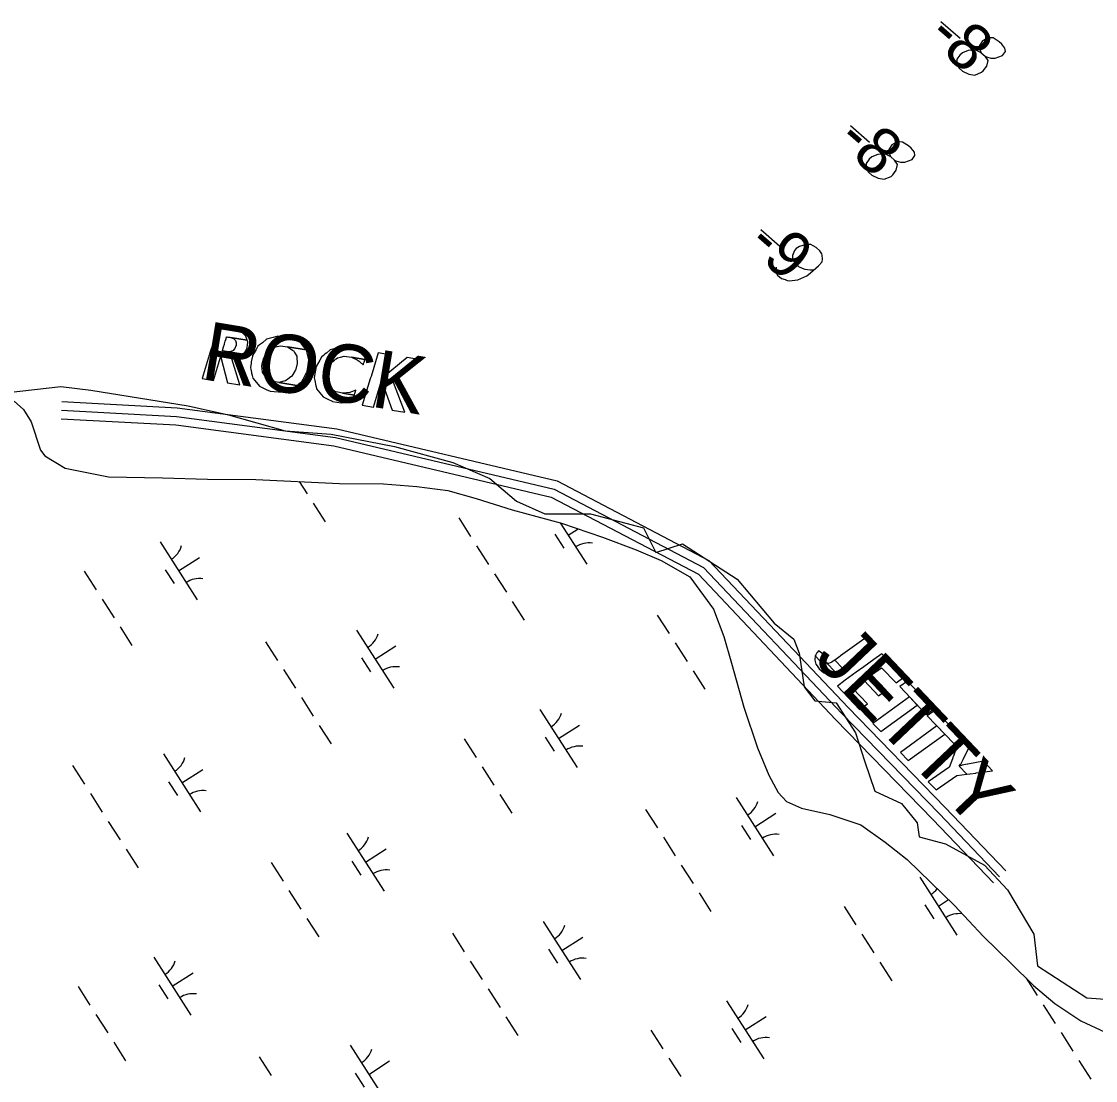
# Model space of a CAD drawing. Extents: x 3962991 to 3983549, y 181631 to 204078.
# Drawn here: x 3969320 to 3970099, y 196180 to 196948 of the extents above; entities that cross this region are included whole.
import ezdxf

# ---------------------------------------------------------------- set-up
doc = ezdxf.new("R2010")
doc.units = 0
for name, color, linetype in [('V-ANNO-MASK', 7, 'Continuous'), ('V-ANNO-MASK2', 7, 'Continuous'), ('V-RIVR-EDGE', 7, 'Continuous'), ('V-RIVR-IDEN', 7, 'Continuous'), ('V-RIVR-RANG', 7, 'Continuous'), ('V-WETL-SWMP', 7, 'Continuous')]:
    doc.layers.add(name, color=color, linetype=linetype)

msp = doc.modelspace()

# ---------------------------------------------------------------- linework, layer by layer
at = {"layer": 'V-ANNO-MASK2'}
for p, q in [((3969986.67, 196948.08), (3970000.6, 196935.96)), ((3969921.03, 196872.65), (3969934.96, 196860.53)), ((3969855.94, 196797.25), (3969869.87, 196785.13))]:
    msp.add_line(p, q, dxfattribs=at)
for points in [[(3970015.92, 196925.43), (3970018.7, 196923.01), (3970019.67, 196922.52), (3970022.93, 196921.43), (3970026.1, 196921.47), (3970031.38, 196923.51), (3970033.43, 196926.27), (3970033.08, 196928.68), (3970030.81, 196931.7), (3970028.82, 196933.43), (3970024.52, 196936.13), (3970021.89, 196936.32), (3970018.97, 196935.37), (3970016.81, 196934.1), (3970014.61, 196930.76), (3970014.37, 196928.88), (3970015.92, 196925.43), (3970012.04, 196927.41), (3970006.46, 196927.02), (3970002.27, 196925.42), (3970000.34, 196923.6), (3969998.11, 196920.65), (3969998.17, 196917.1), (3969999.87, 196914.22), (3970002.26, 196912.15), (3970006.9, 196909.85), (3970011.25, 196909.22), (3970016.15, 196911.24), (3970017.39, 196912.26), (3970019.96, 196915.62), (3970020.8, 196919.79), (3970018.7, 196923.01)], [(3969950.27, 196850), (3969953.06, 196847.57), (3969954.03, 196847.08), (3969957.28, 196846), (3969960.46, 196846.03), (3969965.74, 196848.08), (3969967.79, 196850.84), (3969967.43, 196853.24), (3969965.17, 196856.27), (3969963.18, 196858), (3969958.88, 196860.69), (3969956.25, 196860.88), (3969953.32, 196859.93), (3969951.17, 196858.66), (3969948.97, 196855.33), (3969948.72, 196853.44), (3969950.27, 196850), (3969946.39, 196851.97), (3969940.81, 196851.58), (3969936.62, 196849.98), (3969934.69, 196848.17), (3969932.47, 196845.21), (3969932.53, 196841.66), (3969934.22, 196838.79), (3969936.61, 196836.71), (3969941.26, 196834.41), (3969945.6, 196833.78), (3969950.51, 196835.8), (3969951.75, 196836.82), (3969954.32, 196840.18), (3969955.15, 196844.35), (3969953.06, 196847.57)], [(3969867.18, 196769.99), (3969866.87, 196766.41), (3969868.14, 196764.26), (3969870.93, 196761.83), (3969873.61, 196760.9), (3969875.15, 196760.26), (3969876.66, 196759.99), (3969882.96, 196760.8), (3969889.31, 196763.67), (3969892.16, 196765.74), (3969897.98, 196770.82), (3969900.57, 196773.8), (3969900.82, 196775.69), (3969900.61, 196778.66), (3969900.36, 196779.58), (3969898.89, 196781.91), (3969896.3, 196784.16), (3969893.97, 196785.5), (3969892.23, 196786.31), (3969888.85, 196786.45), (3969884.09, 196785), (3969881.76, 196783.53), (3969880.38, 196781.94), (3969879.12, 196778.48), (3969879.05, 196776.79), (3969879.75, 196774.79), (3969881.62, 196772.11), (3969883.41, 196770.55), (3969886.12, 196769.25), (3969888.03, 196768.63), (3969891.8, 196768.14), (3969893.86, 196768.1), (3969894.98, 196768.18)]]:
    msp.add_lwpolyline(points, dxfattribs=at)
for points in [[(3969456.06, 196706.12), (3969450.9, 196689.14), (3969459.02, 196687.8), (3969464.17, 196704.77), (3969464.3, 196705.19), (3969473.83, 196703.61), (3969474.95, 196703.75), (3969478.33, 196704.92), (3969480.62, 196706.82), (3969465.55, 196709.32), (3969465.55, 196709.33), (3969465.62, 196709.56), (3969465.8, 196710.15), (3969465.93, 196710.57), (3969466.46, 196712.31), (3969467.05, 196714.24), (3969467.08, 196714.36), (3969467.7, 196716.39), (3969468.2, 196718.04), (3969468.3, 196718.37), (3969468.53, 196719.12), (3969468.62, 196719.41), (3969468.63, 196719.42), (3969483.63, 196716.94), (3969482.65, 196719.87), (3969479.54, 196723.02), (3969475.08, 196724.9), (3969469.9, 196725.86), (3969462.43, 196727.09), (3969462.39, 196727), (3969462.07, 196725.92), (3969461.31, 196723.41), (3969460.5, 196720.77), (3969460.5, 196720.76), (3969460.41, 196720.46), (3969460.19, 196719.71), (3969460.08, 196719.38), (3969459.58, 196717.74), (3969458.97, 196715.71), (3969458.93, 196715.59), (3969458.34, 196713.66), (3969457.82, 196711.91), (3969457.69, 196711.5), (3969457.51, 196710.91), (3969457.44, 196710.67), (3969457.44, 196710.66), (3969456.77, 196708.49), (3969456.27, 196706.84), (3969456.18, 196706.53)], [(3969471.05, 196708.66), (3969468.6, 196708.82), (3969480.64, 196706.83), (3969480.88, 196707.03), (3969481.51, 196707.55), (3969481.71, 196707.95), (3969482.58, 196709.64), (3969483.53, 196711.51), (3969483.55, 196711.64), (3969483.54, 196711.64), (3969483.78, 196713.73), (3969483.97, 196715.42), (3969484.02, 196715.76), (3969483.74, 196716.6), (3969483.63, 196716.93), (3969471.51, 196718.93), (3969473.57, 196718.28), (3969474.59, 196717.33), (3969475.05, 196716.9), (3969475.65, 196715.07), (3969475.49, 196712.97), (3969475.44, 196712.85), (3969474.71, 196710.95), (3969473.18, 196709.37), (3969472.29, 196709.08)], [(3969469.53, 196719.27), (3969471.51, 196718.93), (3969483.63, 196716.93), (3969483.63, 196716.94)], [(3969497.33, 196681.33), (3969500.13, 196680.03), (3969509.07, 196679.39), (3969512.02, 196680.35), (3969516.99, 196681.95), (3969519.64, 196684.15), (3969506.4, 196686.35), (3969501.35, 196687.23), (3969497.27, 196689.79), (3969497.21, 196689.89), (3969496.11, 196691.66), (3969496.1, 196691.66), (3969494.7, 196693.91), (3969494.67, 196694.29), (3969494.54, 196695.88), (3969494.3, 196698.93), (3969494.37, 196699.21), (3969494.36, 196699.22), (3969494.54, 196699.91), (3969495.64, 196704.16), (3969495.63, 196704.17), (3969495.65, 196704.24), (3969495.81, 196704.48), (3969497.89, 196707.7), (3969498.6, 196708.8), (3969498.63, 196708.82), (3969501.44, 196710.91), (3969502.74, 196711.86), (3969502.79, 196711.91), (3969507.72, 196713), (3969507.75, 196713.01), (3969512.8, 196712.2), (3969526.57, 196709.92), (3969523.69, 196713.39), (3969521.62, 196715.88), (3969516.51, 196718.25), (3969514.23, 196719.31), (3969514.22, 196719.32), (3969505.69, 196720.04), (3969502.36, 196719.07), (3969497.65, 196717.7), (3969494.6, 196715.21), (3969494.57, 196715.19), (3969494.56, 196715.18), (3969492.61, 196713.59), (3969492.55, 196713.55), (3969491.36, 196712.58), (3969490.01, 196710.24), (3969490, 196710.22), (3969489.36, 196709.11), (3969487.49, 196705.86), (3969487.34, 196705.62), (3969487.3, 196705.54), (3969486.55, 196701.23), (3969486.42, 196700.53), (3969486.38, 196700.24), (3969485.87, 196697.32), (3969486.24, 196695.68), (3969486.33, 196695.3), (3969486.81, 196693.2), (3969487.19, 196691.55), (3969487.21, 196691.46), (3969487.67, 196689.5), (3969487.71, 196689.44), (3969490.21, 196686.38), (3969492.52, 196683.58)], [(3969468.59, 196708.82), (3969466.74, 196709.12), (3969480.62, 196706.82), (3969480.64, 196706.83)], [(3969506.53, 196686.38), (3969506.4, 196686.35), (3969519.64, 196684.15), (3969519.7, 196684.2), (3969519.69, 196684.2), (3969521.58, 196685.77), (3969521.68, 196685.84), (3969521.67, 196685.84), (3969523.27, 196687.16), (3969524.26, 196689.01), (3969524.44, 196689.36), (3969524.44, 196689.36), (3969525.21, 196690.8), (3969526.68, 196693.57), (3969526.83, 196693.84), (3969527.18, 196694.5), (3969527.82, 196698.83), (3969527.84, 196698.91), (3969527.87, 196699.17), (3969528.39, 196702.65), (3969528.08, 196703.91), (3969528.07, 196703.94), (3969527.41, 196706.6), (3969527.11, 196707.83), (3969527.1, 196707.88), (3969526.61, 196709.87), (3969526.59, 196709.89), (3969526.57, 196709.92), (3969512.8, 196712.2), (3969512.85, 196712.16), (3969512.88, 196712.14), (3969516.99, 196709.56), (3969517.1, 196709.49), (3969517.85, 196708.19), (3969519.47, 196705.36), (3969519.48, 196705.34), (3969519.58, 196704.11), (3969519.91, 196700.49), (3969519.84, 196700.23), (3969519.82, 196700.16), (3969518.73, 196695.9), (3969518.55, 196695.21), (3969518.38, 196694.94), (3969516.64, 196692.22), (3969515.73, 196690.8), (3969515.33, 196690.49), (3969513.16, 196688.84), (3969511.45, 196687.54), (3969511.22, 196687.48)], [(3969545.26, 196672.69), (3969545.34, 196672.65), (3969551.77, 196671.61), (3969556.92, 196671.83), (3969559.67, 196672.47), (3969559.96, 196672.53), (3969561.28, 196677.27), (3969552.74, 196678.68), (3969549.31, 196679.3), (3969547.6, 196679.61), (3969544.89, 196681.31), (3969543.52, 196682.17), (3969540.96, 196686.29), (3969540.79, 196688.24), (3969540.55, 196691.31), (3969541.88, 196696.52), (3969541.91, 196696.62), (3969544.85, 196701.16), (3969546.8, 196702.62), (3969547.67, 196703.26), (3969547.99, 196703.5), (3969549.05, 196704.28), (3969551.24, 196704.77), (3969554, 196705.39), (3969559.11, 196704.71), (3969568.97, 196703.07), (3969569.84, 196705.76), (3969570.1, 196706.56), (3969566.79, 196709.06), (3969563.21, 196710.53), (3969560.43, 196711.67), (3969560.43, 196711.67), (3969551.9, 196712.4), (3969549.98, 196711.84), (3969545.72, 196710.6), (3969543.86, 196710.06), (3969540.98, 196707.71), (3969540.8, 196707.57), (3969539.71, 196706.68), (3969538.84, 196705.97), (3969537.87, 196705.18), (3969537.57, 196704.93), (3969537.15, 196704.22), (3969536.21, 196702.59), (3969533.57, 196698), (3969533.51, 196697.9), (3969532.59, 196692.63), (3969532.07, 196689.68), (3969532.53, 196687.68), (3969533.42, 196683.85), (3969533.57, 196683.19), (3969533.87, 196681.89), (3969533.88, 196681.86), (3969533.92, 196681.8), (3969538.61, 196676.07), (3969538.72, 196675.94), (3969542.03, 196674.29)], [(3969464.41, 196704.73), (3969469.32, 196686.09), (3969478.21, 196684.62), (3969472.31, 196703.42), (3969473.83, 196703.61), (3969464.3, 196705.19)], [(3969566.68, 196700.11), (3969567.7, 196699.16), (3969567.94, 196699.9), (3969568.03, 196700.18), (3969568.33, 196701.09), (3969568.59, 196701.9), (3969568.92, 196702.92), (3969568.97, 196703.07), (3969559.11, 196704.71), (3969559.68, 196704.45), (3969563.3, 196702.78), (3969564.71, 196701.69), (3969566.29, 196700.47)], [(3969572.85, 196689.05), (3969567.04, 196669.9), (3969575.15, 196668.56), (3969580.96, 196687.71), (3969589.73, 196686.26), (3969589.48, 196686.94), (3969590.66, 196687.9), (3969581.48, 196689.42), (3969586.68, 196706.51), (3969578.57, 196707.86), (3969573.37, 196690.76), (3969573.04, 196689.67)], [(3969599.5, 196704.39), (3969581.48, 196689.42), (3969590.66, 196687.9), (3969609.11, 196702.8)], [(3969580.96, 196687.71), (3969588.66, 196666.32), (3969597.79, 196664.81), (3969589.73, 196686.26)], [(3969552.94, 196678.7), (3969552.74, 196678.68), (3969561.28, 196677.27), (3969561.29, 196677.32), (3969561.3, 196677.34), (3969561.64, 196678.54), (3969561.8, 196679.14), (3969562.25, 196680.75), (3969559.18, 196679.58), (3969558.03, 196679.14), (3969553.05, 196678.71)], [(3969913.28, 196487.7), (3969909.67, 196485.07), (3969915.31, 196479.13), (3969918.94, 196481.74), (3969919.6, 196482.23), (3969938, 196495.59), (3969932.33, 196501.57), (3969913.94, 196488.18)], [(3969895.96, 196488.81), (3969895.56, 196488.06), (3969907.88, 196475.09), (3969908.86, 196475.22), (3969910.31, 196476.02), (3969910.35, 196476.03), (3969903.34, 196483.41), (3969903.01, 196484.44), (3969902.88, 196484.88), (3969903.37, 196486.07), (3969903.4, 196486.16), (3969903.96, 196486.83), (3969904.1, 196486.98), (3969904.29, 196487.2), (3969903.01, 196488.12), (3969902.13, 196488.75), (3969898.37, 196491.45), (3969897.99, 196491.73), (3969897.22, 196490.84), (3969897.09, 196490.69), (3969896.78, 196490.32), (3969896.75, 196490.3)], [(3969896.87, 196480.82), (3969898.33, 196478.74), (3969901.39, 196476.06), (3969901.85, 196475.89), (3969905.01, 196474.69), (3969905.13, 196474.71), (3969907.88, 196475.09), (3969895.56, 196488.06), (3969895.2, 196485.17), (3969895.25, 196484.97), (3969896.01, 196482.04)], [(3969904.81, 196482.55), (3969903.34, 196483.41), (3969910.35, 196476.03), (3969910.78, 196476.26), (3969910.96, 196476.37), (3969912.03, 196476.94), (3969912.11, 196476.99), (3969912.9, 196477.42), (3969913.08, 196477.51), (3969915.31, 196479.13), (3969909.66, 196485.07), (3969907.37, 196483.53), (3969907.2, 196483.41), (3969906.31, 196483.09), (3969906.22, 196483.06), (3969905.02, 196482.63)], [(3969917.27, 196470.41), (3969911.6, 196466.28), (3969927.69, 196449.34), (3969933.36, 196453.46), (3969922.88, 196464.49), (3969930.88, 196470.32), (3969941.36, 196459.28), (3969946.9, 196463.3), (3969936.42, 196474.34), (3969943.64, 196479.59), (3969954.12, 196468.55), (3969959.78, 196472.66), (3969943.69, 196489.6), (3969938.03, 196485.49), (3969930.81, 196480.25), (3969925.28, 196476.23)], [(3969962.39, 196469.91), (3969956.77, 196465.83), (3969975.98, 196445.6), (3969981.6, 196449.68)], [(3969963.79, 196458.44), (3969937.32, 196439.19), (3969942.99, 196433.22), (3969969.46, 196452.47)], [(3969982.37, 196448.86), (3969976.75, 196444.79), (3969995.96, 196424.56), (3970001.58, 196428.63)], [(3969983.77, 196437.39), (3969957.3, 196418.15), (3969962.97, 196412.18), (3969989.44, 196431.42)], [(3969992.5, 196407.27), (3969977.46, 196396.92), (3969983.14, 196390.94), (3969998.17, 196401.3), (3969998.22, 196401.32), (3970005.53, 196402.33), (3970000, 196408.15), (3970000.97, 196409.59), (3970001.03, 196409.71), (3970002.81, 196412.92), (3970002.89, 196413.09), (3970007.37, 196422.53), (3970001.1, 196429.14), (3969997.16, 196419.13), (3969997.09, 196418.94), (3969995.68, 196415.35), (3969995.62, 196415.22), (3969994.94, 196413.48), (3969992.52, 196407.32)], [(3970001.76, 196408.76), (3970000, 196408.15), (3970005.53, 196402.33), (3970007.59, 196402.62), (3970007.75, 196402.63), (3970012.02, 196403.22), (3970012.23, 196403.25), (3970024.13, 196404.88), (3970017.45, 196411.92), (3970006.13, 196409.68), (3970005.92, 196409.64), (3970001.89, 196408.8)]]:
    msp.add_lwpolyline(points, close=True, dxfattribs=at)
at = {"layer": 'V-RIVR-EDGE'}
msp.add_lwpolyline([(3969290.81, 196677.03), (3969348.44, 196683.43), (3969370.21, 196680.87), (3969440.65, 196669.35), (3969470.1, 196662.94), (3969511.08, 196651.42), (3969544.38, 196648.86), (3969590.48, 196639.89), (3969632.74, 196628.37), (3969659.64, 196616.84), (3969678.85, 196600.19), (3969699.34, 196591.23), (3969732.63, 196591.23), (3969771.05, 196580.98), (3969780.02, 196563.05), (3969799.23, 196569.46), (3969838.93, 196543.84), (3969865.82, 196511.83), (3969879.91, 196500.3), (3969883.75, 196490.06), (3969887.59, 196465.73), (3969895.27, 196455.48), (3969910.64, 196454.2), (3969924.73, 196432.43), (3969931.13, 196411.94), (3969938.82, 196390.17), (3969958.03, 196381.2), (3969969.55, 196367.12), (3969970.83, 196356.87), (3969990.04, 196351.75), (3970018.22, 196336.38), (3970034.86, 196318.45), (3970054.07, 196286.44), (3970056.64, 196263.38), (3970092.49, 196240.33), (3970109.14, 196239.05)], dxfattribs=at)
at = {"layer": 'V-RIVR-IDEN'}
for points in [[(3969349.26, 196672.56), (3969432.9, 196667.99), (3969548.66, 196652.71), (3969708.41, 196615.01), (3969818.39, 196557.39), (3969919.29, 196450.6), (3969989.83, 196378.25), (3970033.73, 196332.33)], [(3969348.92, 196666.32), (3969432.32, 196661.76), (3969547.53, 196646.55), (3969706.21, 196609.11), (3969814.56, 196552.33), (3969914.78, 196446.27), (3969985.33, 196373.91), (3970029.21, 196328.01)], [(3969348.58, 196660.08), (3969431.74, 196655.53), (3969546.4, 196640.4), (3969704, 196603.2), (3969810.74, 196547.28), (3969910.27, 196441.95), (3969980.84, 196369.57), (3970024.7, 196323.69)]]:
    msp.add_lwpolyline(points, dxfattribs=at)
at = {"layer": 'V-WETL-SWMP'}
for p, q in [((3969314.62, 196672.7), (3969321.33, 196666.73)), ((3969321.33, 196666.73), (3969326.88, 196657.73)), ((3969326.88, 196657.73), (3969333.77, 196637.26)), ((3969333.77, 196637.26), (3969336.84, 196633.07)), ((3969336.84, 196633.07), (3969351.45, 196624.17)), ((3969351.45, 196624.17), (3969382.95, 196617.89)), ((3969382.95, 196617.89), (3969422.24, 196617.14)), ((3969422.24, 196617.14), (3969454.89, 196616.31)), ((3969454.89, 196616.31), (3969489.95, 196616.11)), ((3969489.95, 196616.11), (3969550.42, 196613.19)), ((3969521.31, 196614.6), (3969527.08, 196605.59)), ((3969550.42, 196613.19), (3969582.46, 196612.96)), ((3969582.46, 196612.96), (3969606.66, 196610.83)), ((3969606.66, 196610.83), (3969629.05, 196608.07)), ((3969629.05, 196608.07), (3969649.67, 196602.26)), ((3969649.67, 196602.26), (3969675.76, 196594.1)), ((3969531.4, 196598.85), (3969540.04, 196585.38)), ((3969675.76, 196594.1), (3969711.53, 196584.24)), ((3969636.97, 196588.13), (3969645.6, 196574.67)), ((3969710.61, 196584.5), (3969729.83, 196554.52)), ((3969711.53, 196584.24), (3969741.26, 196574.32)), ((3969706.61, 196576.45), (3969713.08, 196566.35)), ((3969716.34, 196575.56), (3969723.6, 196580.22)), ((3969420.37, 196570.79), (3969447.35, 196528.69)), ((3969741.26, 196574.32), (3969765.55, 196564.93)), ((3969649.92, 196567.93), (3969658.56, 196554.46)), ((3969765.55, 196564.93), (3969783.77, 196557.28)), ((3969433.86, 196549.74), (3969449.01, 196559.45)), ((3969783.77, 196557.28), (3969804.46, 196545.44)), ((3969365.46, 196549.49), (3969374.1, 196536.02)), ((3969424.13, 196550.63), (3969430.6, 196540.52)), ((3969662.87, 196547.73), (3969671.51, 196534.26)), ((3969804.46, 196545.44), (3969821.65, 196522.07)), ((3969378.42, 196529.29), (3969387.05, 196515.82)), ((3969675.83, 196527.52), (3969684.46, 196514.05)), ((3969821.65, 196522.07), (3969829.14, 196502.21)), ((3969780.97, 196517.77), (3969789.6, 196504.3)), ((3969391.37, 196509.08), (3969400, 196495.61)), ((3969562.82, 196506.84), (3969589.8, 196464.74)), ((3969496.94, 196498.36), (3969505.57, 196484.89)), ((3969829.14, 196502.21), (3969834.8, 196482.93)), ((3969576.31, 196485.79), (3969591.46, 196495.5)), ((3969793.92, 196497.57), (3969802.56, 196484.1)), ((3969566.58, 196486.68), (3969573.05, 196476.57)), ((3969834.8, 196482.93), (3969843.63, 196451)), ((3969509.89, 196478.16), (3969518.52, 196464.69)), ((3969806.87, 196477.36), (3969815.51, 196463.89)), ((3969522.84, 196457.95), (3969531.48, 196444.48)), ((3969695.84, 196449.29), (3969722.83, 196407.2)), ((3969843.63, 196451), (3969853.65, 196421.5)), ((3969535.8, 196437.75), (3969544.43, 196424.28)), ((3969709.33, 196428.25), (3969724.49, 196437.96)), ((3969699.6, 196429.13), (3969706.08, 196419.03)), ((3969640.94, 196428), (3969649.57, 196414.53)), ((3969853.65, 196421.5), (3969861.74, 196401.65)), ((3969422.79, 196417.06), (3969449.77, 196374.97)), ((3969356.9, 196408.59), (3969365.54, 196395.12)), ((3969436.28, 196396.02), (3969451.43, 196405.73)), ((3969653.89, 196407.79), (3969662.52, 196394.32)), ((3969861.74, 196401.65), (3969868.53, 196389.04)), ((3969426.54, 196396.9), (3969433.02, 196386.8)), ((3969369.86, 196388.38), (3969378.49, 196374.91)), ((3969666.84, 196387.59), (3969675.48, 196374.12)), ((3969838.29, 196385.34), (3969865.28, 196343.25)), ((3969868.53, 196389.04), (3969874.65, 196382.46)), ((3969874.65, 196382.46), (3969885.59, 196377.76)), ((3969772.41, 196376.87), (3969781.04, 196363.4)), ((3969851.78, 196364.3), (3969866.94, 196374.01)), ((3969885.59, 196377.76), (3969906.19, 196373.16)), ((3969382.81, 196368.18), (3969391.45, 196354.71)), ((3969906.19, 196373.16), (3969928.64, 196365.56)), ((3969555.81, 196359.52), (3969582.79, 196317.43)), ((3969842.05, 196365.18), (3969848.53, 196355.08)), ((3969928.64, 196365.56), (3969946.31, 196353.08)), ((3969785.36, 196356.66), (3969794, 196343.19)), ((3969946.31, 196353.08), (3969962.17, 196340.57)), ((3969395.76, 196347.97), (3969404.4, 196334.5)), ((3969569.3, 196338.47), (3969584.46, 196348.19)), ((3969500.9, 196338.22), (3969509.54, 196324.75)), ((3969559.57, 196339.36), (3969566.05, 196329.26)), ((3969798.32, 196336.46), (3969806.95, 196322.99)), ((3969962.17, 196340.57), (3969996.41, 196307.12)), ((3969971.31, 196327.8), (3969998.3, 196285.71)), ((3969513.86, 196318.02), (3969522.49, 196304.55)), ((3969811.27, 196316.25), (3969819.9, 196302.79)), ((3969984.81, 196306.75), (3969992.04, 196311.39)), ((3969916.41, 196306.5), (3969925.04, 196293.03)), ((3969975.07, 196307.64), (3969981.55, 196297.54)), ((3969996.41, 196307.12), (3970017.22, 196285)), ((3969526.81, 196297.81), (3969535.45, 196284.34)), ((3969698.26, 196295.57), (3969725.24, 196253.48)), ((3969632.38, 196287.09), (3969641.01, 196273.63)), ((3969711.75, 196274.52), (3969726.9, 196284.24)), ((3969929.36, 196286.3), (3969938, 196272.83)), ((3970017.22, 196285), (3970037.39, 196265.29)), ((3969702.02, 196275.41), (3969708.49, 196265.31)), ((3969415.78, 196269.75), (3969442.76, 196227.65)), ((3969645.33, 196266.89), (3969653.97, 196253.42)), ((3969942.32, 196266.1), (3969950.95, 196252.63)), ((3970037.39, 196265.29), (3970053.9, 196249.17)), ((3969429.27, 196248.7), (3969444.42, 196258.42)), ((3969419.54, 196249.59), (3969426.01, 196239.49)), ((3970048.45, 196254.48), (3970056.52, 196241.91)), ((3970053.9, 196249.17), (3970069.16, 196236.05)), ((3969360.87, 196248.45), (3969369.51, 196234.98)), ((3969658.28, 196246.69), (3969666.92, 196233.22)), ((3969831.28, 196238.03), (3969858.27, 196195.93)), ((3970060.84, 196235.17), (3970069.47, 196221.7)), ((3970069.16, 196236.05), (3970088.04, 196223.57)), ((3969373.83, 196228.25), (3969382.46, 196214.78)), ((3969671.24, 196226.48), (3969679.87, 196213.01)), ((3969844.78, 196216.98), (3969859.93, 196226.7)), ((3969835.04, 196217.87), (3969841.52, 196207.77)), ((3970088.04, 196223.57), (3970105.67, 196215.32)), ((3969776.38, 196216.73), (3969785.01, 196203.26)), ((3970073.79, 196214.97), (3970082.42, 196201.5)), ((3969386.78, 196208.04), (3969395.41, 196194.57)), ((3969558.23, 196205.8), (3969585.21, 196163.7)), ((3969492.35, 196197.32), (3969500.98, 196183.85)), ((3969789.33, 196196.53), (3969797.97, 196183.06)), ((3970086.74, 196194.76), (3970095.38, 196181.29)), ((3969571.72, 196184.75), (3969586.87, 196194.46)), ((3969561.99, 196185.64), (3969568.46, 196175.53))]:
    msp.add_line(p, q, dxfattribs=at)
for centre, start, end in [((3969701.63, 196598.94), 301.89187, 303.67957), ((3969731.45, 196552.44), 81.89186, 123.43552), ((3969419.15, 196573.12), 301.89187, 343.43553), ((3969448.97, 196526.62), 81.89186, 123.43552), ((3969561.6, 196509.17), 301.89187, 343.43553), ((3969591.42, 196462.66), 81.89186, 123.43552), ((3969694.63, 196451.63), 301.89187, 343.43553), ((3969724.44, 196405.12), 81.89186, 123.43552), ((3969421.57, 196419.4), 301.89187, 343.43553), ((3969451.39, 196372.89), 81.89186, 123.43552), ((3969837.08, 196387.68), 301.89187, 343.43553), ((3969866.89, 196341.17), 81.89186, 123.43552), ((3969554.59, 196361.86), 301.89187, 343.43553), ((3969584.41, 196315.35), 81.89186, 123.43552), ((3969970.1, 196330.14), 301.89187, 321.9379), ((3969999.91, 196283.63), 83.02789, 123.43552), ((3969697.04, 196297.9), 301.89187, 343.43553), ((3969414.56, 196272.08), 301.89187, 343.43553), ((3969726.86, 196251.4), 81.89186, 123.43552), ((3969444.38, 196225.58), 81.89186, 123.43552), ((3969830.07, 196240.36), 301.89187, 343.43553), ((3969859.88, 196193.86), 81.89186, 123.43552), ((3969557.01, 196208.13), 301.89187, 343.43553)]:
    msp.add_arc(centre, 17.62, start, end, dxfattribs=at)

# ---------------------------------------------------------------- texts
at = {"layer": 'V-ANNO-MASK'}
for s, height, rotation, p in [('-8', 33.5, 318.96875, (3969975.59, 196935.35)), ('-8', 33.5, 318.96875, (3969909.95, 196859.91)), ('-9', 33.5, 318.96875, (3969844.86, 196784.52)), ('ROCK', 42, 350.59531, (3969449.21, 196689.42)), ('JETTY', 42, 313.51459, (3969893.6, 196485.25))]:
    msp.add_text(s, height=height, rotation=rotation, dxfattribs=at).set_placement(p)
at = {"layer": 'V-RIVR-IDEN'}
for s, rotation, p in [('ROCK', 350.59531, (3969449.21, 196689.42)), ('JETTY', 313.51459, (3969893.6, 196485.25))]:
    msp.add_text(s, height=42, rotation=rotation, dxfattribs=at).set_placement(p)
at = {"layer": 'V-RIVR-RANG'}
for s, p in [('-8', (3969975.59, 196935.35)), ('-8', (3969909.95, 196859.91)), ('-9', (3969844.86, 196784.52))]:
    msp.add_text(s, height=33.5, rotation=318.96875, dxfattribs=at).set_placement(p)

doc.saveas('drawing.dxf')
